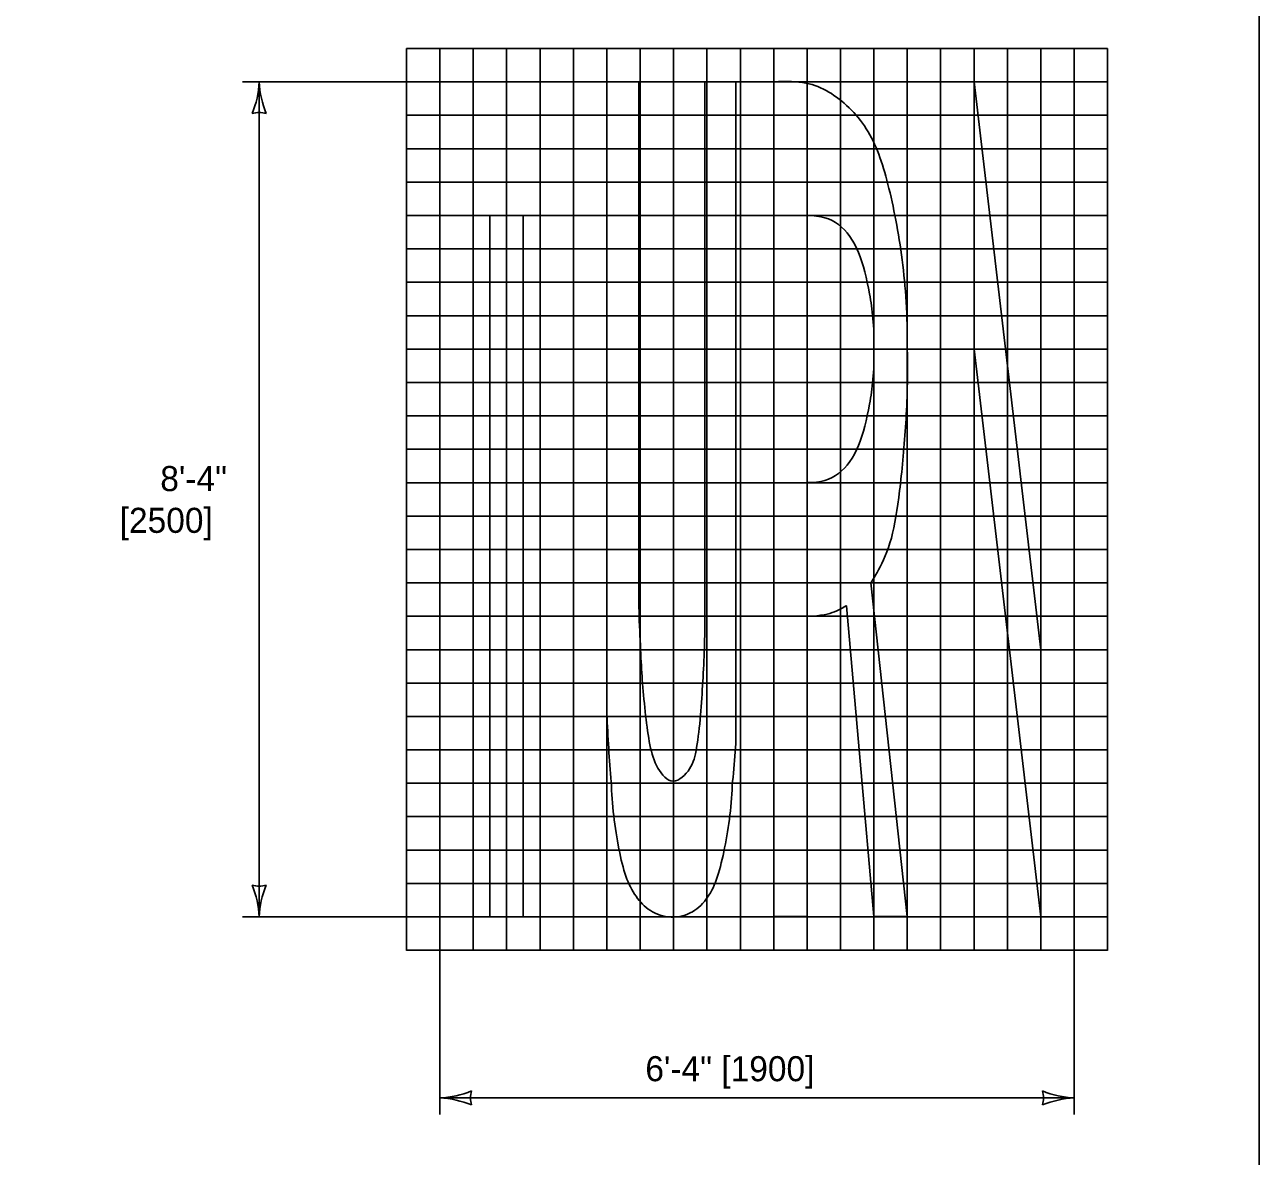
# Model space of a CAD drawing. Extents: x 49991.4 to 50021, y 49987.6 to 50011.4.
# Drawn here: x 50005.656 to 50008.615, y 50005.842 to 50008.552 of the extents above; entities that cross this region are included whole.
import ezdxf

# ---------------------------------------------------------------- set-up
doc = ezdxf.new("R2010")
doc.units = 0
for name, color, linetype in [('Level 1', 7, 'Continuous'), ('Level 2', 7, 'Continuous'), ('Level 3', 7, 'Continuous'), ('Level 9', 7, 'Continuous')]:
    doc.layers.add(name, color=color, linetype=linetype)

msp = doc.modelspace()

# ---------------------------------------------------------------- linework, layer by layer
at = {"layer": 'Level 1'}
for p, q in [((50006.6511, 50008.4153), (50006.6511, 50008.0953)), ((50006.6511, 50008.4153), (50006.9711, 50008.4153)), ((50006.9711, 50008.4153), (50006.6511, 50008.4153)), ((50006.6511, 50008.4153), (50006.6511, 50008.0953)), ((50006.9711, 50008.4153), (50006.6511, 50008.4153)), ((50006.6511, 50008.4153), (50006.6511, 50008.0953)), ((50006.9711, 50008.4153), (50006.6511, 50008.4153)), ((50006.6511, 50008.4153), (50006.6511, 50008.0953)), ((50006.9711, 50008.4153), (50006.9711, 50008.0953)), ((50006.9711, 50008.0953), (50006.9711, 50008.4153)), ((50006.9711, 50008.0953), (50006.9711, 50008.4153)), ((50006.9711, 50008.0953), (50006.9711, 50008.4153)), ((50007.0511, 50006.9012), (50007.0511, 50008.4153)), ((50007.0511, 50008.4153), (50007.1275, 50008.4153)), ((50007.1275, 50007.2193), (50007.1275, 50008.4153)), ((50007.2863, 50007.2185), (50007.2863, 50008.4153)), ((50007.3604, 50008.4153), (50007.2863, 50008.4153)), ((50007.3604, 50006.9031), (50007.3604, 50008.4153)), ((50007.4511, 50006.4158), (50007.4511, 50008.4153)), ((50007.4511, 50006.4158), (50007.4511, 50008.4153)), ((50007.4511, 50006.4158), (50007.4511, 50008.4153)), ((50007.4511, 50006.4158), (50007.4511, 50008.4153)), ((50007.9311, 50008.4153), (50007.8511, 50008.4153)), ((50007.8511, 50008.4153), (50007.8511, 50006.4152)), ((50007.9311, 50008.4153), (50007.8511, 50008.4153)), ((50007.8511, 50008.4153), (50007.8511, 50006.4152)), ((50007.9311, 50008.4153), (50007.8511, 50008.4153)), ((50007.8511, 50008.4153), (50007.8511, 50006.4152)), ((50007.9311, 50008.4153), (50007.8511, 50008.4153)), ((50007.8511, 50008.4153), (50007.8511, 50006.4152)), ((50008.0911, 50007.0552), (50007.9311, 50008.4153)), ((50008.0911, 50007.0552), (50007.9311, 50008.4153)), ((50008.0911, 50007.0552), (50007.9311, 50008.4153)), ((50008.0911, 50007.0552), (50007.9311, 50008.4153)), ((50008.1711, 50008.4153), (50008.0911, 50008.4153)), ((50008.0911, 50008.4153), (50008.0911, 50007.0552)), ((50008.1711, 50008.4153), (50008.0911, 50008.4153)), ((50008.0911, 50008.4153), (50008.0911, 50007.0552)), ((50008.1711, 50008.4153), (50008.0911, 50008.4153)), ((50008.0911, 50008.4153), (50008.0911, 50007.0552)), ((50008.1711, 50008.4153), (50008.0911, 50008.4153)), ((50008.0911, 50008.4153), (50008.0911, 50007.0552)), ((50008.1711, 50006.4152), (50008.1711, 50008.4153)), ((50008.1711, 50006.4152), (50008.1711, 50008.4153)), ((50008.1711, 50006.4152), (50008.1711, 50008.4153)), ((50008.1711, 50006.4152), (50008.1711, 50008.4153)), ((50006.6511, 50008.0953), (50006.7711, 50008.0953)), ((50006.6511, 50008.0953), (50006.7711, 50008.0953)), ((50006.6511, 50008.0953), (50006.7711, 50008.0953)), ((50006.6511, 50008.0953), (50006.7711, 50008.0953)), ((50006.7711, 50008.0953), (50006.7711, 50006.4152)), ((50006.7711, 50008.0953), (50006.7711, 50006.4152)), ((50006.7711, 50008.0953), (50006.7711, 50006.4152)), ((50006.7711, 50008.0953), (50006.7711, 50006.4152)), ((50006.9711, 50008.0953), (50006.8511, 50008.0953)), ((50006.8511, 50008.0953), (50006.8511, 50006.4152)), ((50006.8511, 50006.4152), (50006.8511, 50008.0953)), ((50006.8511, 50008.0953), (50006.9711, 50008.0953)), ((50006.8511, 50006.4152), (50006.8511, 50008.0953)), ((50006.8511, 50008.0953), (50006.9711, 50008.0953)), ((50006.8511, 50006.4152), (50006.8511, 50008.0953)), ((50006.8511, 50008.0953), (50006.9711, 50008.0953)), ((50007.5311, 50007.4555), (50007.5311, 50008.0954)), ((50007.5311, 50008.0954), (50007.5311, 50007.4555)), ((50007.5311, 50008.0954), (50007.5311, 50007.4555)), ((50007.5311, 50008.0954), (50007.5311, 50007.4555)), ((50007.9311, 50006.4152), (50007.9311, 50007.7753)), ((50007.9311, 50007.7753), (50008.0911, 50006.4152)), ((50007.9311, 50006.4152), (50007.9311, 50007.7753)), ((50007.9311, 50007.7753), (50008.0911, 50006.4152)), ((50007.9311, 50006.4152), (50007.9311, 50007.7753)), ((50007.9311, 50007.7753), (50008.0911, 50006.4152)), ((50007.9311, 50006.4152), (50007.9311, 50007.7753)), ((50007.9311, 50007.7753), (50008.0911, 50006.4152)), ((50007.6836, 50007.2156), (50007.7711, 50006.4158)), ((50007.6836, 50007.2156), (50007.7711, 50006.4158)), ((50007.6836, 50007.2156), (50007.7711, 50006.4158)), ((50007.6836, 50007.2156), (50007.7711, 50006.4158)), ((50007.6911, 50006.4158), (50007.6252, 50007.1607)), ((50007.6911, 50006.4158), (50007.6252, 50007.1607)), ((50007.6911, 50006.4158), (50007.6252, 50007.1607)), ((50007.6911, 50006.4158), (50007.6252, 50007.1607)), ((50007.5311, 50007.1356), (50007.5311, 50006.4158)), ((50007.5311, 50007.1356), (50007.5311, 50006.4158)), ((50007.5311, 50007.1356), (50007.5311, 50006.4158)), ((50007.5311, 50007.1356), (50007.5311, 50006.4158)), ((50006.8511, 50006.4152), (50006.7711, 50006.4152)), ((50006.7711, 50006.4152), (50006.8511, 50006.4152)), ((50006.7711, 50006.4152), (50006.8511, 50006.4152)), ((50006.7711, 50006.4152), (50006.8511, 50006.4152)), ((50007.5311, 50006.4158), (50007.4511, 50006.4158)), ((50007.5311, 50006.4158), (50007.4511, 50006.4158)), ((50007.5311, 50006.4158), (50007.4511, 50006.4158)), ((50007.5311, 50006.4158), (50007.4511, 50006.4158)), ((50007.7711, 50006.4158), (50007.6911, 50006.4158)), ((50007.7711, 50006.4158), (50007.6911, 50006.4158)), ((50007.7711, 50006.4158), (50007.6911, 50006.4158)), ((50007.7711, 50006.4158), (50007.6911, 50006.4158)), ((50007.8511, 50006.4152), (50007.9311, 50006.4152)), ((50007.8511, 50006.4152), (50007.9311, 50006.4152)), ((50007.8511, 50006.4152), (50007.9311, 50006.4152)), ((50007.8511, 50006.4152), (50007.9311, 50006.4152)), ((50008.0911, 50006.4152), (50008.1711, 50006.4152)), ((50008.0911, 50006.4152), (50008.1711, 50006.4152)), ((50008.0911, 50006.4152), (50008.1711, 50006.4152)), ((50008.0911, 50006.4152), (50008.1711, 50006.4152))]:
    msp.add_line(p, q, dxfattribs=at)
msp.add_lwpolyline([(50008.6146, 50011.2628), (50000.3356, 50011.2628), (50000.3356, 50000.0624), (50008.6146, 50000.0624)], close=True, dxfattribs=at)
for points in [[(50007.1275, 50007.2193), (50007.1275, 50008.4153), (50007.0511, 50008.4153), (50007.0511, 50006.9012)], [(50007.3604, 50008.4153), (50007.2863, 50008.4153), (50007.2863, 50007.2185)], [(50007.3604, 50006.9031), (50007.3604, 50008.4153)]]:
    msp.add_lwpolyline(points, dxfattribs=at)
for points in [[(50007.4511, 50008.4153), (50007.514, 50008.42), (50007.5841, 50008.4021), (50007.6818, 50008.3091), (50007.7261, 50008.1796), (50007.7626, 50007.9909), (50007.7719, 50007.8563), (50007.7711, 50007.7755)], [(50007.4511, 50008.4153), (50007.514, 50008.42), (50007.5841, 50008.4021), (50007.6818, 50008.3091), (50007.7261, 50008.1796), (50007.7626, 50007.9909), (50007.7719, 50007.8563), (50007.7711, 50007.7755)], [(50007.4511, 50008.4153), (50007.514, 50008.42), (50007.5841, 50008.4021), (50007.6818, 50008.3091), (50007.7261, 50008.1796), (50007.7626, 50007.9909), (50007.7719, 50007.8563), (50007.7711, 50007.7755)], [(50007.4511, 50008.4153), (50007.514, 50008.42), (50007.5841, 50008.4021), (50007.6818, 50008.3091), (50007.7261, 50008.1796), (50007.7626, 50007.9909), (50007.7719, 50007.8563), (50007.7711, 50007.7755)], [(50007.5311, 50008.0954), (50007.5632, 50008.0953), (50007.6108, 50008.0818), (50007.6576, 50008.0121), (50007.6822, 50007.9107), (50007.6924, 50007.8302), (50007.6911, 50007.7755)], [(50007.6911, 50007.7755), (50007.6924, 50007.8302), (50007.6822, 50007.9107), (50007.6576, 50008.0121), (50007.6108, 50008.0818), (50007.5632, 50008.0953), (50007.5311, 50008.0954)], [(50007.6911, 50007.7755), (50007.6924, 50007.8302), (50007.6822, 50007.9107), (50007.6576, 50008.0121), (50007.6108, 50008.0818), (50007.5632, 50008.0953), (50007.5311, 50008.0954)], [(50007.6911, 50007.7755), (50007.6924, 50007.8302), (50007.6822, 50007.9107), (50007.6576, 50008.0121), (50007.6108, 50008.0818), (50007.5632, 50008.0953), (50007.5311, 50008.0954)], [(50007.6911, 50007.7755), (50007.6924, 50007.7207), (50007.6822, 50007.6402), (50007.6576, 50007.5388), (50007.6108, 50007.4691), (50007.5632, 50007.4556), (50007.5311, 50007.4555)], [(50007.5311, 50007.4555), (50007.5632, 50007.4556), (50007.6108, 50007.4691), (50007.6576, 50007.5388), (50007.6822, 50007.6402), (50007.6924, 50007.7207), (50007.6911, 50007.7755)], [(50007.5311, 50007.4555), (50007.5632, 50007.4556), (50007.6108, 50007.4691), (50007.6576, 50007.5388), (50007.6822, 50007.6402), (50007.6924, 50007.7207), (50007.6911, 50007.7755)], [(50007.5311, 50007.4555), (50007.5632, 50007.4556), (50007.6108, 50007.4691), (50007.6576, 50007.5388), (50007.6822, 50007.6402), (50007.6924, 50007.7207), (50007.6911, 50007.7755)], [(50007.7711, 50007.7755), (50007.7724, 50007.6952), (50007.7688, 50007.5884), (50007.7528, 50007.4281), (50007.736, 50007.3171), (50007.701, 50007.2397), (50007.6836, 50007.2156), (50007.6836, 50007.2156)], [(50007.7711, 50007.7755), (50007.7724, 50007.6952), (50007.7688, 50007.5884), (50007.7528, 50007.4281), (50007.736, 50007.3171), (50007.701, 50007.2397), (50007.6836, 50007.2156), (50007.6836, 50007.2156)], [(50007.7711, 50007.7755), (50007.7724, 50007.6952), (50007.7688, 50007.5884), (50007.7528, 50007.4281), (50007.736, 50007.3171), (50007.701, 50007.2397), (50007.6836, 50007.2156), (50007.6836, 50007.2156)], [(50007.7711, 50007.7755), (50007.7724, 50007.6952), (50007.7688, 50007.5884), (50007.7528, 50007.4281), (50007.736, 50007.3171), (50007.701, 50007.2397), (50007.6836, 50007.2156), (50007.6836, 50007.2156)], [(50007.1275, 50007.2193), (50007.1277, 50007.1921), (50007.128, 50007.1386), (50007.1328, 50007.039), (50007.1361, 50006.9771), (50007.144, 50006.896), (50007.1534, 50006.8246), (50007.1694, 50006.7702), (50007.2092, 50006.7256), (50007.2554, 50006.77), (50007.2665, 50006.8145), (50007.2769, 50006.899), (50007.281, 50006.9791), (50007.2857, 50007.0592), (50007.2865, 50007.1391), (50007.2864, 50007.1923), (50007.2863, 50007.2185)], [(50007.2863, 50007.2185), (50007.2864, 50007.1923), (50007.2865, 50007.1391), (50007.2857, 50007.0592), (50007.281, 50006.9791), (50007.2769, 50006.899), (50007.2665, 50006.8145), (50007.2554, 50006.77), (50007.2092, 50006.7256), (50007.1694, 50006.7702), (50007.1534, 50006.8246), (50007.144, 50006.896), (50007.1361, 50006.9771), (50007.1328, 50007.039), (50007.128, 50007.1386), (50007.1277, 50007.1921), (50007.1275, 50007.2193)], [(50007.6252, 50007.1607), (50007.6252, 50007.1607), (50007.5975, 50007.144), (50007.5665, 50007.1361), (50007.5311, 50007.1356)], [(50007.6252, 50007.1607), (50007.6252, 50007.1607), (50007.5975, 50007.144), (50007.5665, 50007.1361), (50007.5311, 50007.1356)], [(50007.6252, 50007.1607), (50007.6252, 50007.1607), (50007.5975, 50007.144), (50007.5665, 50007.1361), (50007.5311, 50007.1356)], [(50007.6252, 50007.1607), (50007.6252, 50007.1607), (50007.5975, 50007.144), (50007.5665, 50007.1361), (50007.5311, 50007.1356)], [(50007.0511, 50006.9012), (50007.0525, 50006.8736), (50007.0554, 50006.8191), (50007.0617, 50006.7383), (50007.066, 50006.6581), (50007.0802, 50006.575), (50007.0952, 50006.5099), (50007.1201, 50006.4625), (50007.1518, 50006.4281), (50007.2055, 50006.4091), (50007.2599, 50006.4243), (50007.2943, 50006.4599), (50007.3177, 50006.5091), (50007.3338, 50006.579), (50007.3481, 50006.6591), (50007.3517, 50006.7393), (50007.3614, 50006.8205), (50007.3607, 50006.8745), (50007.3604, 50006.9031)], [(50007.0511, 50006.9012), (50007.0525, 50006.8736), (50007.0554, 50006.8191), (50007.0617, 50006.7383), (50007.066, 50006.6581), (50007.0802, 50006.575), (50007.0952, 50006.5099), (50007.1201, 50006.4625), (50007.1518, 50006.4281), (50007.2055, 50006.4091), (50007.2599, 50006.4243), (50007.2943, 50006.4599), (50007.3177, 50006.5091), (50007.3338, 50006.579), (50007.3481, 50006.6591), (50007.3517, 50006.7393), (50007.3614, 50006.8205), (50007.3607, 50006.8745), (50007.3604, 50006.9031)]]:
    msp.add_open_spline(points, degree=3, dxfattribs=at)
at = {"layer": 'Level 3'}
for p, q in [((50006.6111, 50008.4153), (50006.1783, 50008.4153)), ((50006.2183, 50008.4153), (50006.2183, 50006.4153)), ((50006.6511, 50008.0553), (50006.6511, 50005.9416)), ((50006.6111, 50006.4153), (50006.1783, 50006.4153)), ((50006.7311, 50006.4153), (50006.6911, 50006.4153)), ((50008.1711, 50006.3752), (50008.1711, 50005.9416)), ((50006.6511, 50005.9816), (50008.1707, 50005.9816))]:
    msp.add_line(p, q, dxfattribs=at)
for centre, radius, start, end in [((50005.9961, 50008.4245), 0.2223, 337.456, 357.6395), ((50006.451, 50008.4268), 0.233, 182.8273, 202.0772), ((50006.2183, 50008.2871), 0.0548, 72.1388, 107.8612), ((50006.2183, 50006.5435), 0.0548, 252.1388, 287.8612), ((50005.9856, 50006.4038), 0.233, 2.8273, 22.0772), ((50006.4404, 50006.4061), 0.2223, 157.456, 177.6395), ((50006.6419, 50006.2037), 0.2223, 272.3605, 292.544), ((50006.7793, 50005.9816), 0.0548, 162.1388, 197.8612), ((50008.1803, 50006.2037), 0.2223, 247.456, 267.6395), ((50008.0429, 50005.9816), 0.0548, 342.1388, 17.8612), ((50006.6396, 50005.7489), 0.233, 67.9228, 87.1727), ((50008.1826, 50005.7489), 0.233, 92.8273, 112.0772)]:
    msp.add_arc(centre, radius, start, end, dxfattribs=at)
at = {"layer": 'Level 9'}
for p, q in [((50006.5711, 50008.4953), (50006.5711, 50006.3345)), ((50006.5711, 50008.4953), (50008.2511, 50008.4953)), ((50006.6511, 50008.4953), (50006.6511, 50006.3345)), ((50006.7311, 50008.4953), (50006.7311, 50006.3345)), ((50006.8111, 50008.4953), (50006.8111, 50006.3345)), ((50006.8911, 50008.4953), (50006.8911, 50006.3345)), ((50006.9711, 50008.4953), (50006.9711, 50006.3345)), ((50007.0511, 50008.4953), (50007.0511, 50006.3345)), ((50007.1311, 50008.4953), (50007.1311, 50006.3345)), ((50007.2111, 50008.4953), (50007.2111, 50006.3345)), ((50007.2911, 50008.4953), (50007.2911, 50006.3345)), ((50007.3711, 50008.4953), (50007.3711, 50006.3345)), ((50007.4511, 50008.4953), (50007.4511, 50006.3345)), ((50007.5311, 50008.4953), (50007.5311, 50006.3345)), ((50007.6111, 50008.4953), (50007.6111, 50006.3345)), ((50007.6911, 50008.4953), (50007.6911, 50006.3345)), ((50007.7711, 50008.4953), (50007.7711, 50006.3345)), ((50007.8511, 50008.4953), (50007.8511, 50006.3345)), ((50007.9311, 50008.4953), (50007.9311, 50006.3345)), ((50008.0111, 50008.4953), (50008.0111, 50006.3345)), ((50008.0911, 50008.4953), (50008.0911, 50006.3345)), ((50008.1711, 50008.4953), (50008.1711, 50006.3345)), ((50008.2511, 50008.4953), (50008.2511, 50006.3345)), ((50006.5711, 50008.4153), (50008.2511, 50008.4153)), ((50006.5711, 50008.3353), (50008.2511, 50008.3353)), ((50006.5711, 50008.2553), (50008.2511, 50008.2553)), ((50006.5711, 50008.1753), (50008.2511, 50008.1753)), ((50006.6474, 50008.1752), (50008.0981, 50008.1752)), ((50006.5711, 50008.0953), (50008.2511, 50008.0953)), ((50006.6474, 50008.0952), (50008.0981, 50008.0952)), ((50006.5711, 50008.0153), (50008.2511, 50008.0153)), ((50006.5711, 50007.9353), (50008.2511, 50007.9353)), ((50006.5711, 50007.8553), (50008.2511, 50007.8553)), ((50006.5711, 50007.7753), (50008.2511, 50007.7753)), ((50006.5711, 50007.6953), (50008.2511, 50007.6953)), ((50006.5711, 50007.6153), (50008.2511, 50007.6153)), ((50006.5711, 50007.5353), (50008.2511, 50007.5353)), ((50006.5711, 50007.4553), (50008.2511, 50007.4553)), ((50006.5711, 50007.3753), (50008.2511, 50007.3753)), ((50006.5711, 50007.2953), (50008.2511, 50007.2953)), ((50006.5711, 50007.2153), (50008.2511, 50007.2153)), ((50006.5711, 50007.1353), (50008.2511, 50007.1353)), ((50006.5711, 50007.0553), (50008.2511, 50007.0553)), ((50006.5711, 50006.9753), (50008.2511, 50006.9753)), ((50006.5711, 50006.8953), (50008.2511, 50006.8953)), ((50006.5711, 50006.8153), (50008.2511, 50006.8153)), ((50006.5711, 50006.7353), (50008.2511, 50006.7353)), ((50006.5711, 50006.6553), (50008.2511, 50006.6553)), ((50006.5711, 50006.5753), (50008.2511, 50006.5753)), ((50006.5711, 50006.4953), (50008.2511, 50006.4953)), ((50006.5711, 50006.4153), (50008.2511, 50006.4153)), ((50006.5711, 50006.3353), (50008.2511, 50006.3353))]:
    msp.add_line(p, q, dxfattribs=at)

# ---------------------------------------------------------------- texts
at = {"layer": 'Level 2'}
for s, p in [('8\'-4"', (50005.9813, 50007.4351)), ('[2500]', (50005.884, 50007.3351)), ('6\'-4" [1900]', (50007.1435, 50006.0216))]:
    msp.add_text(s, height=0.06, dxfattribs=at).set_placement(p)

doc.saveas('drawing.dxf')
